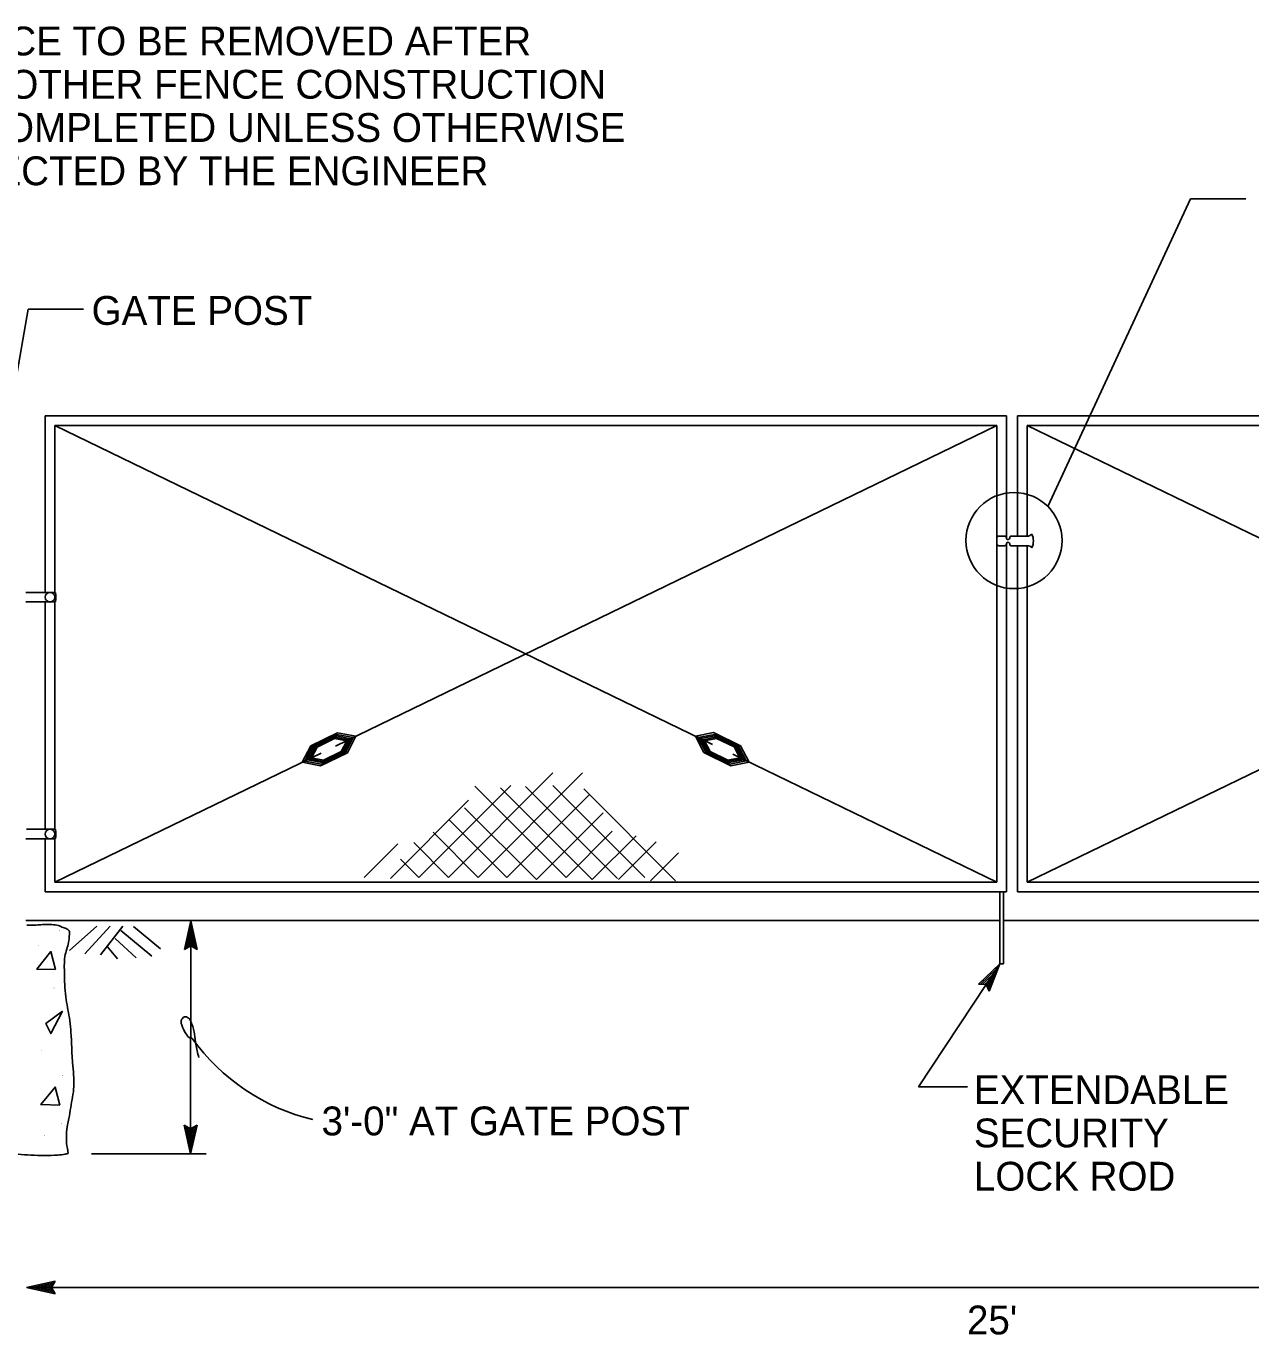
# Model space of a CAD drawing. Extents: x -123486 to -116575, y -107066 to -101122.
# Drawn here: x -118359.8 to -118104.9, y -102096.7 to -101824.4 of the extents above; entities that cross this region are included whole.
import ezdxf

# ---------------------------------------------------------------- set-up
doc = ezdxf.new("R2010")
doc.units = 0
for name, color, linetype in [('G-MARK', 7, 'Continuous'), ('G-TEXT', 7, 'Continuous'), ('Misc CnstDet(22)', 7, 'Continuous'), ('Nongeo Data(60)', 7, 'Continuous')]:
    doc.layers.add(name, color=color, linetype=linetype)

msp = doc.modelspace()

# ---------------------------------------------------------------- linework, layer by layer
at = {"layer": 'G-MARK'}
for p, q in [((-118117.49, -101860.34), (-118105.99, -101860.34)), ((-118359.31, -101883.3), (-118347.81, -101883.3)), ((-118325.54, -102059.03), (-118325.49, -102010.52)), ((-118174.06, -102045.09), (-118157.18, -102019.46)), ((-118161.6, -102023.73), (-118157.18, -102019.46)), ((-118157.18, -102019.46), (-118159.37, -102025.2)), ((-118157.18, -102019.46), (-118157.18, -102019.46)), ((-118161.18, -102023.75), (-118157.94, -102020.61)), ((-118160.75, -102023.75), (-118158.7, -102021.76)), ((-118158.7, -102021.76), (-118159.73, -102024.47)), ((-118157.94, -102020.62), (-118159.54, -102024.81)), ((-118160.04, -102023.8), (-118161.6, -102023.73)), ((-118161.6, -102023.73), (-118161.6, -102023.73)), ((-118160.36, -102023.79), (-118159.46, -102022.92)), ((-118159.37, -102025.2), (-118160.04, -102023.8)), ((-118159.46, -102022.92), (-118159.9, -102024.07)), ((-118159.37, -102025.2), (-118159.37, -102025.2)), ((-118163.93, -102045.09), (-118174.06, -102045.09)), ((-118346.16, -102059.01), (-118322.28, -102059.01)), ((-118359.71, -102086.81), (-117947.29, -102086.81))]:
    msp.add_line(p, q, dxfattribs=at)
for points in [[(-118147.15, -101924.36), (-118117.49, -101860.34), (-118117.49, -101860.34)], [(-118362.16, -101899.67), (-118359.31, -101883.3)]]:
    msp.add_lwpolyline(points, dxfattribs=at)
msp.add_circle((-118154.22, -101931.43), 10, dxfattribs=at)
msp.add_arc((-118290.15, -102009.95), 43.08, 215.5482, 256.6593, dxfattribs=at)
msp.add_spline([(-118325.2, -102035), (-118325.53, -102034.95), (-118326.51, -102033.97), (-118327.4, -102032.19), (-118327.4, -102031.03), (-118326.6, -102030.5), (-118325.8, -102030.94), (-118325.26, -102032.01), (-118324.73, -102034.15), (-118324.46, -102036.19), (-118323.84, -102038.95)], degree=3, dxfattribs=at)
at = {"layer": 'G-TEXT'}
for p, q in [((-118326.84, -102016.52), (-118325.49, -102010.52)), ((-118325.49, -102010.52), (-118325.49, -102010.52)), ((-118325.49, -102010.52), (-118324.17, -102016.53)), ((-118326.48, -102016.31), (-118325.49, -102011.9)), ((-118326.12, -102016.07), (-118325.49, -102013.29)), ((-118325.49, -102011.92), (-118324.52, -102016.29)), ((-118325.49, -102013.29), (-118324.87, -102016.11)), ((-118325.49, -102015.72), (-118326.84, -102016.52)), ((-118326.84, -102016.52), (-118326.84, -102016.52)), ((-118325.77, -102015.9), (-118325.5, -102014.67)), ((-118325.5, -102014.67), (-118325.23, -102015.88)), ((-118324.17, -102016.53), (-118325.49, -102015.72)), ((-118324.17, -102016.53), (-118324.17, -102016.53)), ((-118325.54, -102059.03), (-118326.86, -102053.03)), ((-118326.86, -102053.03), (-118326.86, -102053.03)), ((-118326.86, -102053.03), (-118325.53, -102053.83)), ((-118325.54, -102057.64), (-118326.5, -102053.27)), ((-118325.53, -102056.27), (-118326.16, -102053.44)), ((-118325.53, -102054.89), (-118325.8, -102053.68)), ((-118324.19, -102053.03), (-118325.54, -102059.03)), ((-118324.55, -102053.25), (-118325.54, -102057.65)), ((-118325.53, -102053.83), (-118324.19, -102053.03)), ((-118324.91, -102053.48), (-118325.53, -102056.27)), ((-118325.26, -102053.66), (-118325.53, -102054.89)), ((-118324.19, -102053.03), (-118324.19, -102053.03)), ((-118325.54, -102059.03), (-118325.54, -102059.03)), ((-118359.71, -102086.81), (-118353.71, -102085.48)), ((-118353.71, -102088.15), (-118359.71, -102086.81)), ((-118359.71, -102086.81), (-118359.71, -102086.81)), ((-118353.93, -102087.79), (-118358.33, -102086.81)), ((-118358.32, -102086.8), (-118353.94, -102085.84)), ((-118356.95, -102086.81), (-118354.12, -102086.18)), ((-118354.16, -102087.43), (-118356.95, -102086.81)), ((-118355.57, -102086.81), (-118354.36, -102086.54)), ((-118354.34, -102087.08), (-118355.57, -102086.81)), ((-118353.71, -102085.48), (-118354.51, -102086.81)), ((-118354.51, -102086.81), (-118353.71, -102088.15)), ((-118353.71, -102085.48), (-118353.71, -102085.48)), ((-118353.71, -102088.15), (-118353.71, -102088.15))]:
    msp.add_line(p, q, dxfattribs=at)
at = {"layer": 'Misc CnstDet(22)'}
msp.add_lwpolyline([(-118156.41, -102004.5), (-118156.41, -102019.46), (-118157.18, -102019.46), (-118157.18, -102004.5)], dxfattribs=at)
at = {"layer": 'Nongeo Data(60)'}
for p, q in [((-118355.8, -101942.23), (-118355.8, -101905.5)), ((-118155.8, -101905.5), (-118355.8, -101905.5)), ((-118155.8, -101930.83), (-118155.8, -101905.5)), ((-117953.48, -101905.5), (-118153.48, -101905.5)), ((-118153.48, -101930.47), (-118153.48, -101905.5)), ((-118353.8, -101942.2), (-118353.8, -101907.5)), ((-118353.8, -101907.5), (-118216.92, -101973.84)), ((-118157.8, -101907.5), (-118353.8, -101907.5)), ((-118157.8, -101907.5), (-118295.36, -101974.18)), ((-118157.8, -101930.47), (-118157.8, -101907.5)), ((-117955.48, -101907.5), (-118151.48, -101907.5)), ((-118151.48, -101907.5), (-118014.61, -101973.84)), ((-118151.48, -101930.5), (-118151.48, -101907.5)), ((-118157.8, -102002.5), (-118157.8, -101930.47)), ((-118156.23, -101930.5), (-118157.37, -101930.5)), ((-118156.23, -101932.5), (-118157.37, -101932.5)), ((-118155.8, -101930.85), (-118155.8, -101930.83)), ((-118155.8, -102004.5), (-118155.8, -101932.15)), ((-118151.48, -101930.5), (-118154.87, -101930.5)), ((-118151.48, -101932.5), (-118154.83, -101932.5)), ((-118153.48, -101930.5), (-118153.48, -101930.47)), ((-118153.48, -102004.5), (-118153.48, -101932.5)), ((-118151.48, -102002.5), (-118151.48, -101932.5)), ((-118355.8, -101942.2), (-118355.8, -101938.93)), ((-118353.67, -101942.2), (-118359.8, -101942.2)), ((-118353.67, -101944.2), (-118359.8, -101944.2)), ((-118355.8, -101988.23), (-118355.8, -101944.07)), ((-118355.8, -101946.85), (-118355.8, -101944.2)), ((-118353.8, -101991.5), (-118353.8, -101944.2)), ((-118294.95, -101971.42), (-118300.52, -101974.13)), ((-118295.13, -101971.76), (-118300.15, -101974.2)), ((-118295.29, -101972.07), (-118299.81, -101974.27)), ((-118295.44, -101972.35), (-118299.5, -101974.33)), ((-118295.57, -101972.6), (-118299.22, -101974.38)), ((-118293.07, -101973.08), (-118295.57, -101972.6)), ((-118292.67, -101972.88), (-118295.44, -101972.35)), ((-118292.21, -101972.66), (-118295.29, -101972.07)), ((-118291.71, -101972.41), (-118295.13, -101971.76)), ((-118291.15, -101972.14), (-118294.95, -101971.42)), ((-118294.24, -101975.33), (-118293.07, -101973.08)), ((-118293.96, -101975.38), (-118292.67, -101972.88)), ((-118293.65, -101975.44), (-118292.21, -101972.66)), ((-118293.31, -101975.5), (-118291.71, -101972.41)), ((-118292.93, -101975.57), (-118291.15, -101972.14)), ((-118220.51, -101972.11), (-118216.72, -101971.39)), ((-118218.74, -101975.55), (-118220.51, -101972.11)), ((-118219.96, -101972.39), (-118216.54, -101971.74)), ((-118218.36, -101975.48), (-118219.96, -101972.39)), ((-118219.45, -101972.64), (-118216.38, -101972.05)), ((-118218.01, -101975.42), (-118219.45, -101972.64)), ((-118219, -101972.87), (-118216.23, -101972.34)), ((-118217.71, -101975.37), (-118219, -101972.87)), ((-118218.6, -101973.07), (-118216.1, -101972.59)), ((-118217.43, -101975.32), (-118218.6, -101973.07)), ((-118216.72, -101971.39), (-118211.14, -101974.1)), ((-118216.54, -101971.74), (-118211.52, -101974.18)), ((-118216.38, -101972.05), (-118211.86, -101974.25)), ((-118216.23, -101972.34), (-118212.17, -101974.31)), ((-118216.1, -101972.59), (-118212.45, -101974.37)), ((-118298.39, -101975.64), (-118353.8, -102002.5)), ((-118300.52, -101974.13), (-118302.3, -101977.56)), ((-118300.15, -101974.2), (-118301.75, -101977.29)), ((-118299.81, -101974.27), (-118301.25, -101977.05)), ((-118299.5, -101974.33), (-118300.8, -101976.83)), ((-118299.22, -101974.38), (-118300.39, -101976.63)), ((-118298.5, -101978.28), (-118292.93, -101975.57)), ((-118298.33, -101977.94), (-118293.31, -101975.5)), ((-118298.17, -101977.63), (-118293.65, -101975.44)), ((-118298.03, -101977.36), (-118293.96, -101975.38)), ((-118297.9, -101977.11), (-118294.24, -101975.33)), ((-118213.16, -101978.26), (-118218.74, -101975.55)), ((-118213.34, -101977.92), (-118218.36, -101975.48)), ((-118213.5, -101977.62), (-118218.01, -101975.42)), ((-118213.64, -101977.34), (-118217.71, -101975.37)), ((-118213.77, -101977.1), (-118217.43, -101975.32)), ((-118212.75, -101975.86), (-118157.8, -102002.5)), ((-118212.45, -101974.37), (-118211.28, -101976.62)), ((-118212.17, -101974.31), (-118210.87, -101976.82)), ((-118211.86, -101974.25), (-118210.42, -101977.03)), ((-118211.52, -101974.18), (-118209.92, -101977.27)), ((-118211.14, -101974.1), (-118209.36, -101977.54)), ((-118096.07, -101975.64), (-118151.48, -102002.5)), ((-118302.3, -101977.56), (-118298.5, -101978.28)), ((-118301.75, -101977.29), (-118298.33, -101977.94)), ((-118301.25, -101977.05), (-118298.17, -101977.63)), ((-118300.8, -101976.83), (-118298.03, -101977.36)), ((-118300.39, -101976.63), (-118297.9, -101977.11)), ((-118211.28, -101976.62), (-118213.77, -101977.1)), ((-118210.87, -101976.82), (-118213.64, -101977.34)), ((-118210.42, -101977.03), (-118213.5, -101977.62)), ((-118209.92, -101977.27), (-118213.34, -101977.92)), ((-118209.36, -101977.54), (-118213.16, -101978.26)), ((-118271.88, -102001.49), (-118250.16, -101979.77)), ((-118265.7, -102001.49), (-118243.99, -101979.77)), ((-118278.05, -102001.49), (-118258.94, -101982.38)), ((-118247.43, -102001.49), (-118266.42, -101982.5)), ((-118241.97, -102001.96), (-118261.08, -101982.86)), ((-118259.77, -102001.49), (-118242.45, -101984.16)), ((-118236.75, -102001.73), (-118255.86, -101982.62)), ((-118231.05, -102001.49), (-118250.16, -101982.38)), ((-118224.65, -102002.2), (-118243.75, -101983.1)), ((-118283.98, -102001.73), (-118267.72, -101985.47)), ((-118253.6, -102001.96), (-118268.55, -101987.01)), ((-118355.8, -101991.5), (-118355.8, -101988.23)), ((-118355.8, -101991.44), (-118355.8, -101988.23)), ((-118259.77, -102001.49), (-118271.76, -101989.5)), ((-118253.6, -102001.96), (-118239.72, -101988.08)), ((-118353.67, -101991.5), (-118359.69, -101991.5)), ((-118265.7, -102001.49), (-118275.08, -101992.11)), ((-118247.43, -102001.49), (-118237.82, -101991.88)), ((-118353.67, -101993.5), (-118359.8, -101993.5)), ((-118355.8, -101996.14), (-118355.8, -101993.5)), ((-118353.8, -101996.14), (-118353.8, -101993.5)), ((-118353.8, -101996.14), (-118353.8, -101993.5)), ((-118289.44, -102001.49), (-118282.44, -101994.49)), ((-118271.88, -102001.49), (-118279.11, -101994.25)), ((-118241.97, -102001.96), (-118232.83, -101992.83)), ((-118236.51, -102001.96), (-118228.68, -101994.13)), ((-118355.8, -102004.5), (-118355.8, -101996.14)), ((-118353.8, -102002.5), (-118353.8, -101996.14)), ((-118278.05, -102001.49), (-118281.84, -101997.69)), ((-118229.87, -102002.2), (-118224.05, -101996.39)), ((-118157.8, -102002.5), (-118353.8, -102002.5)), ((-117955.48, -102002.5), (-118151.48, -102002.5)), ((-118155.8, -102004.5), (-118355.8, -102004.5)), ((-117953.48, -102004.5), (-118153.48, -102004.5)), ((-118157.18, -102010.5), (-118359.8, -102010.5)), ((-118345.02, -102011.62), (-118350.72, -102016.7)), ((-118342.28, -102011.66), (-118347.57, -102017.42)), ((-118339.61, -102011.66), (-118344.31, -102017.64)), ((-118337.42, -102011.69), (-118331.78, -102016.33)), ((-118153.48, -102010.5), (-118156.41, -102010.5)), ((-117949.48, -102010.5), (-118153.48, -102010.5)), ((-118341.25, -102014.21), (-118336.85, -102018.22)), ((-118340.07, -102012.56), (-118333.63, -102017.86)), ((-118342.81, -102015.93), (-118340.75, -102018.46))]:
    msp.add_line(p, q, dxfattribs=at)
for points in [[(-118353.64, -102020.69), (-118357.55, -102020.58), (-118354.59, -102016.92)], [(-118352.17, -102029.36), (-118354.64, -102034.01), (-118355.67, -102031.93)], [(-118352.78, -102048.88), (-118356.68, -102048.78), (-118353.73, -102045.12)]]:
    msp.add_lwpolyline(points, close=True, dxfattribs=at)
for centre in [(-118354.8, -101943.21), (-118354.79, -101992.49)]:
    msp.add_circle(centre, 1, dxfattribs=at)
for centre, radius, start, end in [((-118151.41, -101929.32), 1.18, 266.4373, 320.9406), ((-118153.78, -101931.5), 3.59, 336.5119, 23.6238), ((-118157.36, -101930.95), 0.45, 90.9719, 166.9649), ((-118157.36, -101932.05), 0.45, 193.0351, 269.0281), ((-118156.24, -101930.95), 0.45, 13.0351, 89.0281), ((-118156.24, -101932.05), 0.45, 270.9719, 346.9649), ((-118155.43, -101930.86), 0.368, 177.9728, 273.0727), ((-118155.43, -101932.14), 0.368, 86.9273, 182.0272), ((-118155.62, -101930.72), 0.552, 292.64, 356.8611), ((-118155.62, -101932.28), 0.552, 3.1389, 67.36), ((-118154.85, -101930.72), 0.223, 82.9178, 185.5923), ((-118154.85, -101932.27), 0.223, 174.4077, 277.0822), ((-118151.4, -101933.68), 1.18, 39.0594, 93.5627)]:
    msp.add_arc(centre, radius, start, end, dxfattribs=at)
for centre in [(-118353.67, -101943.2), (-118353.67, -101992.5)]:
    msp.add_ellipse(centre, major_axis=(0, -1), ratio=0.098201, start_param=0, end_param=3.141593, dxfattribs=at)
for points in [[(-118350.77, -102013.4), (-118350.77, -102012.79), (-118351.2, -102012.27), (-118352.06, -102011.93), (-118353.09, -102011.5), (-118354.38, -102011.33), (-118356.36, -102011.33), (-118357.65, -102011.41), (-118359.02, -102011.41), (-118359.63, -102011.41)], [(-118350.99, -102058.92), (-118351.33, -102056.84), (-118351.14, -102053), (-118350.86, -102051.69), (-118350.49, -102049.35), (-118349.83, -102045.05), (-118350.11, -102040.09), (-118350.3, -102036.26), (-118350.49, -102033.17), (-118350.77, -102030.74), (-118351.52, -102026.34), (-118351.8, -102021.19), (-118351.61, -102017.55), (-118350.86, -102014.65), (-118350.77, -102013.4)], [(-118373.99, -102058.92), (-118372.38, -102059.27), (-118370.51, -102058.99), (-118366.02, -102058.43), (-118363.86, -102058.71), (-118361.43, -102059.08), (-118358.81, -102059.27), (-118355.91, -102059.36), (-118353.2, -102059.27), (-118351.61, -102059.08), (-118350.99, -102058.92)]]:
    msp.add_spline(points, degree=3, dxfattribs=at)

# ---------------------------------------------------------------- texts
at = {"layer": 'Misc CnstDet(22)'}
for s, p in [('BRACE TO BE REMOVED AFTER', (-118379.96, -101830.5)), ('ALL OTHER FENCE CONSTRUCTION', (-118379.96, -101839.5)), ('IS COMPLETED UNLESS OTHERWISE', (-118379.96, -101848.5)), ('DIRECTED BY THE ENGINEER', (-118379.96, -101857.5)), ('GATE POST', (-118346.14, -101886.55)), ('EXTENDABLE', (-118162.57, -102048.67)), ('3\'-0" AT GATE POST', (-118298.3, -102055.17)), ('SECURITY', (-118162.57, -102057.67)), ('LOCK ROD', (-118162.57, -102066.67))]:
    msp.add_text(s, height=6, dxfattribs=at).set_placement(p)
at = {"layer": 'Nongeo Data(60)'}
for p in [(-118352.9, -102012.41), (-118357.19, -102015.57), (-118354.03, -102024.37), (-118356.61, -102037.44), (-118352.3, -102042.61), (-118356.03, -102054.99), (-118352.45, -102052.59)]:
    msp.add_text('.', height=0.8, rotation=266.9315, dxfattribs=at).set_placement(p)
msp.add_text("25'", height=6, dxfattribs=at).set_placement((-118164.01, -102096.58))

doc.saveas('drawing.dxf')
